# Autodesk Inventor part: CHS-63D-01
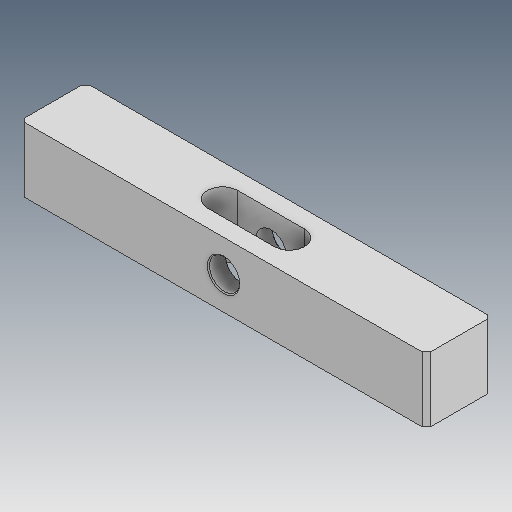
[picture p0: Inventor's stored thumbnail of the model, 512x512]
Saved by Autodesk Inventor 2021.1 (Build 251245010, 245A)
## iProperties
Created: 2019-05
Part Number: CHS-63D-01
Material: Ogólny
Document SubType Name: Modeling
Designer: user
Density: 1 g/cm^3
Appearance: Domyślna
Author: user
Revision Number: ÈÎºÎ
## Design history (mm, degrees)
feature "ÊäÈë1"
node "Bryła1"
